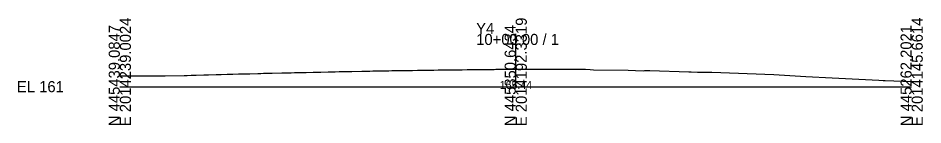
# Model space of a CAD drawing. Extents: x -26 to 203, y -10 to 4021.
# Drawn here: x -25.7 to 202.8, y -9.7 to 17.4 of the extents above; entities that cross this region are included whole.
import ezdxf

# ---------------------------------------------------------------- set-up
doc = ezdxf.new("R2010")
doc.units = 0
for name, color, linetype in [('Default', 7, 'Continuous'), ('Exist Cross Section Cell', 7, 'Continuous'), ('Exist XS Center Line Elevation Label', 7, 'Continuous'), ('Exist XS Ground Line', 7, 'Continuous')]:
    doc.layers.add(name, color=color, linetype=linetype)

msp = doc.modelspace()

# ---------------------------------------------------------------- linework, layer by layer
at = {"layer": 'Exist Cross Section Cell'}
for p, q in [((100, 0), (100, 13.36)), ((0, 0), (100, 0)), ((100, 0), (200, 0))]:
    msp.add_line(p, q, dxfattribs=at)
at = {"layer": 'Exist XS Ground Line'}
msp.add_lwpolyline([(0, 2.78), (11.42, 2.78), (16.26, 2.82), (16.99, 2.83), (17.98, 2.88), (18.86, 2.93), (19.32, 2.94), (21.18, 3), (21.88, 3.01), (22.4, 3.03), (24.36, 3.08), (25.62, 3.11), (27.13, 3.14), (28.57, 3.18), (30.01, 3.21), (30.98, 3.24), (32.31, 3.27), (32.8, 3.29), (34.86, 3.34), (35.65, 3.36), (36.33, 3.38), (37.76, 3.43), (38.48, 3.44), (40.95, 3.51), (41.32, 3.52), (41.64, 3.52), (43.27, 3.53), (44.11, 3.57), (47.05, 3.62), (48.81, 3.66), (49.79, 3.68), (50.76, 3.7), (52.61, 3.74), (54.35, 3.78), (55.44, 3.8), (56.07, 3.81), (58.26, 3.87), (58.59, 3.87), (61.16, 3.93), (62.37, 3.95), (63.12, 3.96), (63.91, 3.98), (65.38, 4), (67.26, 4.04), (67.95, 4.04), (68.7, 4.06), (69.56, 4.07), (70.88, 4.09), (72.38, 4.11), (73.95, 4.13), (75.21, 4.15), (76.69, 4.17), (78.03, 4.19), (78.43, 4.19), (79.34, 4.21), (80.37, 4.23), (80.85, 4.23), (82.64, 4.26), (83.97, 4.27), (84.56, 4.28), (85.88, 4.29), (86.5, 4.3), (87.7, 4.31), (89.6, 4.34), (90.07, 4.34), (91.47, 4.35), (92.16, 4.36), (94.57, 4.38), (94.98, 4.39), (95.31, 4.39), (97.81, 4.41), (100, 4.44), (100.74, 4.45), (103.47, 4.44), (104.42, 4.43), (106.39, 4.44), (109.13, 4.41), (109.91, 4.41), (111.36, 4.41), (111.95, 4.42), (112.66, 4.41), (114.8, 4.4), (116.59, 4.39), (117.59, 4.39), (118.83, 4.37), (119.62, 4.3), (128.37, 4.19), (130.22, 4.09), (132.18, 4.04), (132.52, 4.08), (133.87, 4.06), (143.73, 3.76), (144.32, 3.75), (145.92, 3.71), (146.35, 3.7), (149.51, 3.63), (165.18, 3.06), (173.3, 2.59), (179.88, 2.27), (191.68, 1.63), (192.83, 1.6), (193.35, 1.57), (200, 1.34)], dxfattribs=at)

# ---------------------------------------------------------------- texts
at = {"layer": 'Default'}
msp.add_text('-', height=0.0001, dxfattribs=at).set_placement((0, 0))
at = {"layer": 'Exist Cross Section Cell'}
for s, p in [('E 2014239.0024', (2.8, -10)), ('E 2014192.3319', (102.8, -10)), ('E 2014145.6614', (202.8, -10)), ('N 445439.0847', (0, -10)), ('N 445350.6434', (100, -10)), ('N 445262.2021', (200, -10))]:
    msp.add_text(s, height=2.8, rotation=90, dxfattribs=at).set_placement(p)
for s, p in [('Y4', (90, 13.36)), ('10+00.00 / 1', (90, 10.56)), ('EL 161', (-26, -1.4))]:
    msp.add_text(s, height=2.8, dxfattribs=at).set_placement(p)
at = {"layer": 'Exist XS Center Line Elevation Label'}
msp.add_text('165.44', height=2, dxfattribs=at).set_placement((95.96, -0.56))

doc.saveas('drawing.dxf')
